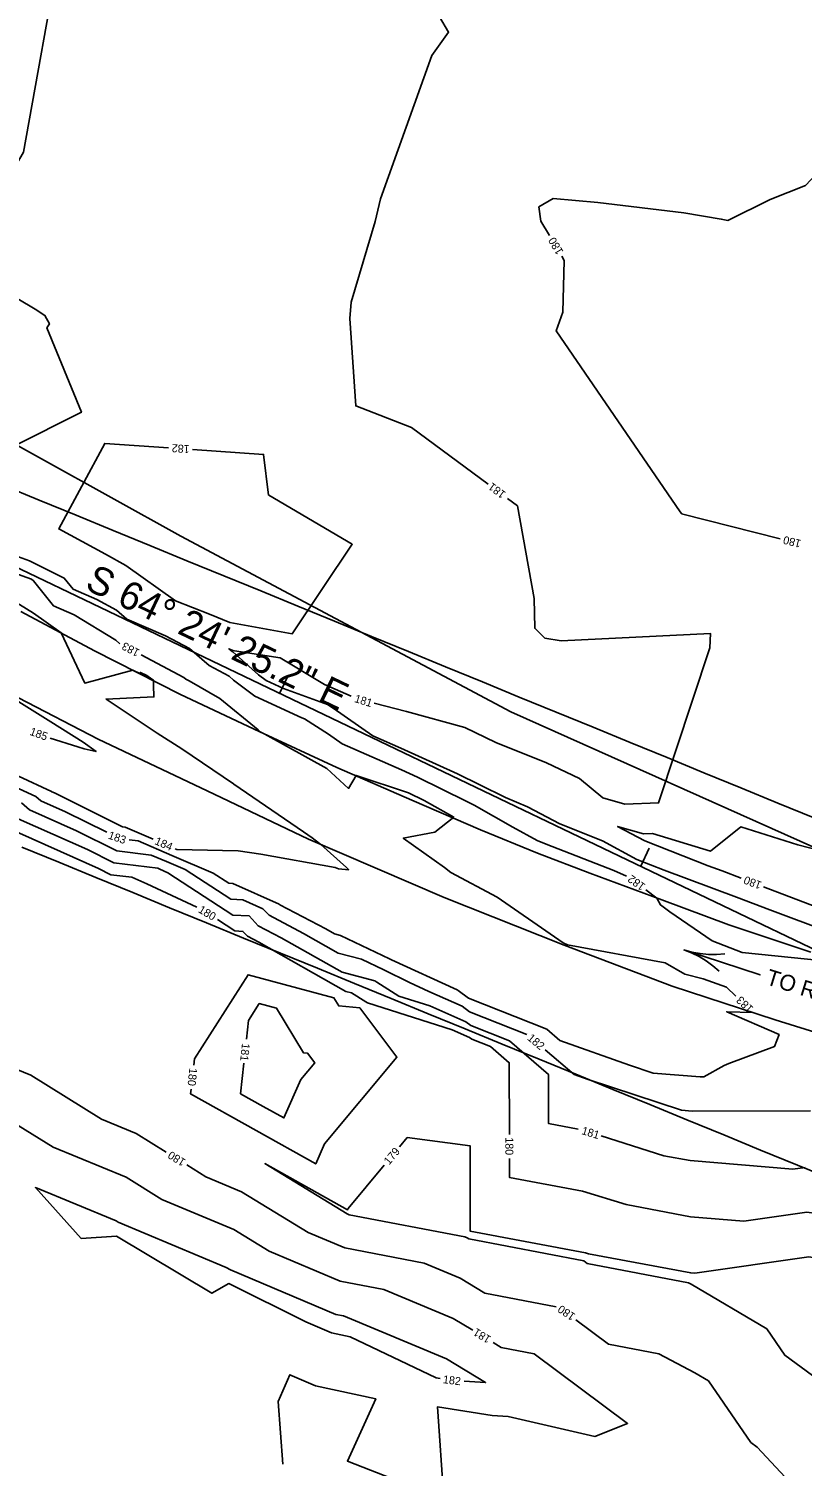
# Model space of a CAD drawing. Extents: x 2086416 to 2115205, y 575507 to 632762.
# Drawn here: x 2110664.3 to 2110857.5, y 581552.3 to 581911.5 of the extents above; entities that cross this region are included whole.
import ezdxf

# ---------------------------------------------------------------- set-up
doc = ezdxf.new("R2010")
doc.units = 0
for name, color, linetype in [('Default', 7, 'Continuous'), ('DTM Contours Major', 7, 'Continuous'), ('DTM Contours Major Text', 7, 'Continuous'), ('DTM Contours Minor', 7, 'Continuous'), ('DTM Contours Minor Text', 7, 'Continuous'), ('Exist Hydrographic FEMA Cross Section', 7, 'Continuous'), ('Exist Roads EOP', 7, 'Continuous'), ('Exist Roads EOP Text', 7, 'Continuous'), ('Exist Vegetation Woods Line', 7, 'Continuous')]:
    doc.layers.add(name, color=color, linetype=linetype)

msp = doc.modelspace()

# ---------------------------------------------------------------- linework, layer by layer
at = {"layer": 'Default'}
for p, q in [((2110456.37, 581874.95), (2110974.98, 581626.56)), ((2110726.94, 581745.36), (2110729.1, 581749.87)), ((2110817.13, 581702.16), (2110819.29, 581706.67))]:
    msp.add_line(p, q, dxfattribs=at)
at = {"layer": 'DTM Contours Major'}
for points in [[(2110875.11, 581887.46), (2110869.25, 581883.98), (2110858.27, 581872.27), (2110849.5, 581868.78), (2110838.87, 581863.56), (2110837.24, 581863.88), (2110827.93, 581865.43), (2110806.43, 581868), (2110795.23, 581869.03), (2110791.72, 581866.92), (2110792.22, 581863.37), (2110794.35, 581859.78)], [(2110797.42, 581854.62), (2110798.05, 581853.55), (2110797.69, 581840.6), (2110795.99, 581835.94), (2110827.03, 581790.7), (2110827.32, 581790.29), (2110827.36, 581790.26), (2110852, 581783.99)], [(2110613.93, 581787.13), (2110614.2, 581786.7), (2110617.97, 581783.15), (2110627.86, 581773.78), (2110633.68, 581769.53), (2110635.48, 581767.5), (2110642.91, 581758.9), (2110656.28, 581747.21), (2110658.07, 581745.98), (2110659.68, 581744.77), (2110661.17, 581743.69), (2110669.84, 581738.28), (2110677.86, 581733.15), (2110681.1, 581730.87), (2110678.11, 581731.54), (2110676.51, 581732.02), (2110669.66, 581734.22)], [(2110706.28, 581691.93), (2110693.8, 581697.81), (2110690.01, 581699.43), (2110684.82, 581700.07), (2110681.7, 581701.62), (2110658.82, 581711.83), (2110658.38, 581712.2), (2110655.34, 581713.32), (2110650.98, 581714.55), (2110621.94, 581701.5), (2110616.68, 581704.25), (2110614.73, 581705.26)], [(2110873.53, 581703.08), (2110856.38, 581707.56), (2110842.13, 581711.99), (2110834.59, 581705.91), (2110820.11, 581710.34), (2110817.82, 581710.24), (2110811.38, 581712.14), (2110818.2, 581708.5), (2110833.97, 581702.31), (2110837.45, 581701), (2110842.24, 581699.17)], [(2110847.85, 581697.03), (2110861.11, 581691.96), (2110865.83, 581690.2), (2110868.29, 581689.26), (2110879.23, 581683.6), (2110880.71, 581683.05), (2110888.09, 581682.6), (2110898.02, 581678.3), (2110910.04, 581674.42), (2110913.9, 581674.27), (2110914.63, 581674.08), (2110929.32, 581669.43), (2110931.83, 581667.74), (2110941.39, 581664.51), (2110941.63, 581664.47)], [(2110784.33, 581635.17), (2110784.32, 581653.09), (2110779.63, 581657.15), (2110774.99, 581658.99), (2110774.4, 581659.43), (2110770.07, 581661.34), (2110748.91, 581668.01), (2110748.44, 581668.31), (2110744.94, 581670.52), (2110743.47, 581670.91), (2110721.78, 581683.2), (2110718.94, 581684.68), (2110717.79, 581685.89), (2110715.79, 581686.01), (2110711.42, 581688.85)], [(2110614.54, 581679.26), (2110619.08, 581680.34), (2110637.66, 581668.88), (2110655.14, 581658.09), (2110656.42, 581653.38), (2110664.82, 581649.96), (2110682.42, 581638.95), (2110691.1, 581635.36), (2110698.64, 581630.7)], [(2110738.13, 581632.78), (2110756.23, 581654.5), (2110746.95, 581666.78), (2110741.73, 581667.28), (2110740.52, 581669.29), (2110719.05, 581675.06), (2110705.66, 581654.02), (2110705.49, 581652.46)], [(2110704.85, 581646.49), (2110704.72, 581645.3), (2110721.08, 581636.15), (2110735.97, 581627.82), (2110738.13, 581632.78)], [(2110876.9, 581608.98), (2110875.97, 581608.94), (2110861.02, 581615.41), (2110858.67, 581615.72), (2110842.9, 581613.47), (2110829.57, 581614.6), (2110813.49, 581617.62), (2110802.61, 581621.03), (2110784.33, 581624.43), (2110784.33, 581629.17)], [(2110703.74, 581627.54), (2110708.49, 581624.6), (2110717.43, 581620.86), (2110734.08, 581610.65), (2110743.22, 581606.79), (2110763.09, 581602.99), (2110772.06, 581599.26), (2110778.24, 581595.53), (2110796.02, 581592.11)], [(2110800.95, 581588.81), (2110809.09, 581582.72), (2110821.66, 581580.31), (2110830.66, 581575.58), (2110834.04, 581573.59), (2110844.63, 581558.22), (2110846.26, 581557.03), (2110861.48, 581540.67), (2110862.45, 581535.67), (2110855.94, 581535.48), (2110849.88, 581541.19)]]:
    msp.add_lwpolyline(points, dxfattribs=at)
at = {"layer": 'DTM Contours Minor'}
for points in [[(2110775.86, 581953.5), (2110764.32, 581958.22), (2110760.24, 581943.47), (2110768.82, 581917.19), (2110766.89, 581914.46), (2110769.13, 581910.61), (2110764.97, 581904.78), (2110752.13, 581868.98), (2110750.83, 581863.28), (2110744.81, 581843.13), (2110744.47, 581839.04), (2110745.98, 581817.21), (2110759.85, 581811.8), (2110779.05, 581797.65)], [(2110672.37, 581932.97), (2110662.96, 581880.6), (2110650.69, 581859.37), (2110649.72, 581851), (2110665.85, 581841.38), (2110668.3, 581839.83), (2110669.46, 581837.68), (2110668.83, 581836.73), (2110677.42, 581815.61), (2110643.22, 581798.5), (2110629.19, 581802.12), (2110627.72, 581804.48), (2110627.29, 581802.33), (2110628.54, 581801.21), (2110629.18, 581800.63), (2110629.48, 581800.67), (2110633.9, 581797.89)], [(2110699.21, 581806.73), (2110683.26, 581807.82), (2110671.77, 581786.48), (2110683.44, 581780.2), (2110688.54, 581777.3), (2110700.9, 581768.53), (2110709.47, 581765.13), (2110714.47, 581763.07)], [(2110714.47, 581763.07), (2110730.11, 581760.27), (2110745.1, 581782.66), (2110724.29, 581794.88), (2110724.2, 581794.91), (2110722.93, 581805.1), (2110705.19, 581806.32)], [(2110783.88, 581794.09), (2110786.38, 581792.24), (2110790.55, 581769.06), (2110790.67, 581761.66), (2110793.22, 581759.21), (2110797.3, 581758.53), (2110834.58, 581760.33), (2110834.42, 581756.77), (2110821.6, 581718.02), (2110813.16, 581717.66), (2110807.7, 581719.27), (2110801.81, 581724.13), (2110793.61, 581728.02), (2110780.97, 581733.08), (2110773.17, 581736.89), (2110758.67, 581740.86), (2110750.54, 581742.89)], [(2110659.86, 581780.13), (2110664.5, 581778.47), (2110673.17, 581774.14), (2110675.37, 581771.42), (2110681.32, 581768.8), (2110686.2, 581766.18), (2110688.77, 581763.93), (2110698.41, 581759.72), (2110704.41, 581756.57), (2110709.32, 581752.37), (2110714.34, 581749.66), (2110715.43, 581748.68), (2110720.79, 581744.69), (2110732.5, 581739.25), (2110733.16, 581739.01), (2110739.12, 581735.16), (2110742.54, 581732.77), (2110757.35, 581726.29), (2110761.4, 581724.45), (2110773.69, 581718.38), (2110775.58, 581717.45), (2110785.2, 581711.98), (2110791.25, 581708.61), (2110793.49, 581707.73), (2110810.4, 581701.16), (2110813.56, 581699.74)], [(2110653.98, 581777.82), (2110665, 581773.88), (2110665.48, 581773.5), (2110670.48, 581767.29), (2110675.64, 581765.02), (2110686.01, 581758.67), (2110687.06, 581757.75)], [(2110654.46, 581772.18), (2110665.46, 581765.46), (2110672.35, 581760.51), (2110678.29, 581747.94), (2110690.29, 581751.21), (2110691.99, 581750.37), (2110692.19, 581750.63), (2110693.8, 581749.81), (2110695.06, 581748.94), (2110695.41, 581748.69), (2110695.46, 581747.45), (2110695.55, 581744.5), (2110683.59, 581743.96), (2110696.4, 581735.45), (2110702.5, 581731.53), (2110715.41, 581722.75), (2110715.47, 581722.71), (2110732.91, 581710.78), (2110735.1, 581709.24), (2110737.26, 581707.64), (2110743.62, 581701.84), (2110744.21, 581701.3), (2110741.62, 581701.53), (2110740.86, 581701.85), (2110722.22, 581705.24), (2110716.61, 581706.04), (2110712.68, 581706.13), (2110701.37, 581706.37), (2110701.31, 581706.38), (2110701.24, 581706.39), (2110700.82, 581706.57)], [(2110692.36, 581754.97), (2110702.99, 581749.38), (2110703.53, 581748.93), (2110704.33, 581748.49), (2110711.97, 581744.12), (2110721.57, 581736.26), (2110722.09, 581735.79), (2110723.27, 581735.2), (2110738.74, 581726.59), (2110744.19, 581721.64), (2110746.05, 581724.86), (2110759.16, 581720.54), (2110763.09, 581718.65), (2110770.46, 581714.45), (2110765.74, 581710.68), (2110757.84, 581709.2), (2110768.09, 581701.86), (2110769.74, 581700.6), (2110781.3, 581694.48), (2110795.58, 581684.55), (2110797.77, 581683.02), (2110798.85, 581682.54), (2110823.21, 581678.05), (2110828.17, 581675.21), (2110832.75, 581674.08), (2110838.55, 581671.95), (2110840.9, 581669.72)], [(2110744.84, 581744.68), (2110738.18, 581747.62), (2110727.08, 581754.3), (2110715.7, 581756.04), (2110715.25, 581756.12), (2110714.3, 581756.51), (2110715.11, 581755.81), (2110715.25, 581755.74), (2110721.64, 581750.04), (2110723.61, 581748.57), (2110727.93, 581746.56), (2110738.89, 581742.6), (2110740.3, 581741.69), (2110750.22, 581734.74), (2110757.2, 581731.69), (2110771.37, 581725.27), (2110776.96, 581722.51), (2110783.38, 581719.36), (2110788.87, 581717), (2110796.93, 581712.8), (2110807.57, 581708.49), (2110816.16, 581703.9), (2110822.98, 581701.22), (2110841.1, 581694.44), (2110849.4, 581691.27), (2110864.3, 581685.71)], [(2110695.32, 581708.96), (2110688.38, 581711.98), (2110687.7, 581712.06), (2110670.71, 581720.49), (2110670.08, 581720.77), (2110669.96, 581720.88), (2110653.37, 581728.55)], [(2110683.75, 581710.67), (2110673.46, 581715.77), (2110667.27, 581718.53), (2110666.02, 581719.6), (2110658.64, 581723.02)], [(2110788.71, 581660.14), (2110774.39, 581665.82), (2110772.51, 581667.23), (2110764.23, 581670.88), (2110759.35, 581673.12), (2110752.95, 581676.29), (2110747.39, 581678.96), (2110741.61, 581680.5), (2110732.94, 581685.41), (2110724.31, 581689.93), (2110722.74, 581691.58), (2110717.79, 581693.79), (2110714.74, 581693.96), (2110703.39, 581701.35), (2110698.68, 581703.34), (2110694.89, 581704.99), (2110686.26, 581706.07), (2110676.21, 581711.05), (2110664.45, 581716.3), (2110662.47, 581718.01)], [(2110801.48, 581636.52), (2110794.09, 581637.9), (2110794.08, 581650.15), (2110784.33, 581658.58), (2110774.69, 581662.4), (2110773.46, 581663.33), (2110764.45, 581667.3), (2110756.74, 581669.73), (2110751.23, 581673.2), (2110750.71, 581673.53), (2110742.54, 581675.71), (2110727.36, 581684.3), (2110721.62, 581687.31), (2110719.3, 581689.75), (2110715.26, 581689.99), (2110699.06, 581700.52), (2110697.04, 581701.47), (2110696.5, 581701.71), (2110685.54, 581703.07), (2110678.96, 581706.34), (2110661.63, 581714.06)], [(2110845.22, 581665.6), (2110838.61, 581665.84), (2110851.69, 581660.12), (2110850.58, 581657.12), (2110839.13, 581652.88), (2110837.96, 581652.36), (2110832.9, 581649.56), (2110831.96, 581649.56), (2110820.28, 581650.5), (2110814.3, 581652.46), (2110796.93, 581658.68), (2110793.73, 581661.45), (2110774.09, 581669.24), (2110771.57, 581671.12), (2110771.27, 581671.26), (2110754.92, 581678.76), (2110754.43, 581679.01), (2110742.11, 581684.91), (2110740.67, 581685.29), (2110738.52, 581686.51), (2110726.99, 581692.55), (2110726.82, 581692.73), (2110715.25, 581697.88), (2110714.22, 581697.94), (2110710.36, 581700.45), (2110700, 581704.85), (2110691.63, 581708.49), (2110689.36, 581708.77)], [(2110818.44, 581696.27), (2110821.2, 581694.21), (2110822.09, 581692.5), (2110824.38, 581690.77), (2110834.99, 581683.55), (2110842.52, 581680.61), (2110862.89, 581678.56)], [(2110604.39, 581671.28), (2110610.61, 581661.99), (2110624.31, 581665.25), (2110632.56, 581660.16), (2110640.32, 581655.37), (2110643.15, 581644.99), (2110661.66, 581637.44), (2110670.37, 581631.99), (2110688.6, 581624.45), (2110697.54, 581618.92), (2110715.51, 581611.4), (2110724.37, 581605.97), (2110742.09, 581598.48), (2110752.98, 581596.4), (2110770.33, 581589.17), (2110775.18, 581586.24)], [(2110732.22, 581648.91), (2110735.7, 581653.09), (2110733.91, 581655.45), (2110732.91, 581655.54), (2110726.18, 581666.71), (2110721.86, 581667.87), (2110719.16, 581663.63), (2110718.66, 581658.97)], [(2110859.55, 581641.04), (2110830.03, 581640.99), (2110827.32, 581641.21), (2110803.98, 581648.87), (2110800.48, 581650.12), (2110793.31, 581656.32)], [(2110718.03, 581653), (2110717.21, 581645.33), (2110722.87, 581642.16), (2110728.03, 581639.28), (2110732.22, 581648.91)], [(2110929.04, 581613.04), (2110920.49, 581613.95), (2110917.95, 581613.11), (2110916.27, 581613.41), (2110901.27, 581603.04), (2110890.27, 581602.57), (2110889.9, 581602.71), (2110866.52, 581601.67), (2110860.13, 581604.43), (2110859.13, 581604.56), (2110830.62, 581600.5), (2110829.64, 581600.58), (2110804.08, 581605.37), (2110803.32, 581605.61), (2110774.57, 581610.97), (2110774.57, 581632.28), (2110758.83, 581634.4), (2110756.92, 581632.1)], [(2110858.22, 581626.88), (2110855.17, 581626.45), (2110829.5, 581628.62), (2110822.89, 581629.86), (2110807.22, 581634.78)], [(2110753.08, 581627.49), (2110744.05, 581616.65), (2110743.92, 581616.36), (2110723.28, 581627.9), (2110743.8, 581615.32), (2110744.35, 581615.09), (2110773.2, 581609.58), (2110773.78, 581609.34), (2110774.18, 581609.1), (2110802.91, 581603.58), (2110803.77, 581602.94), (2110829.06, 581598.07), (2110829.72, 581597.73), (2110848.6, 581586.56), (2110853.13, 581580), (2110864.1, 581571.94), (2110868.48, 581567.23)], [(2110742.87, 581589.81), (2110740.96, 581590.18), (2110714.65, 581601.3), (2110713.6, 581601.94), (2110686.58, 581613.24), (2110686.1, 581613.54), (2110665.95, 581621.88), (2110677.38, 581609.19), (2110686.18, 581609.76), (2110710, 581595.5), (2110714.28, 581597.88), (2110733.49, 581588.34), (2110739.88, 581585.59), (2110744.53, 581584.59), (2110766.06, 581574.38), (2110767.08, 581574.21)], [(2110773.03, 581573.48), (2110778.41, 581573.17), (2110768.6, 581579.09), (2110742.87, 581589.81)], [(2110780.32, 581583.14), (2110782.3, 581581.95), (2110790.5, 581580.38), (2110813.88, 581562.9), (2110805.64, 581559.71), (2110784.07, 581564.67), (2110780.03, 581564.9), (2110766.38, 581567.1), (2110767.94, 581544.14), (2110743.89, 581553.54), (2110750.95, 581569.13), (2110735.94, 581572.34), (2110729.52, 581575.11), (2110726.6, 581568.42), (2110727.73, 581552.75)]]:
    msp.add_lwpolyline(points, dxfattribs=at)
at = {"layer": 'Exist Hydrographic FEMA Cross Section'}
for points in [[(2110860.61, 581714.19), (2110851.39, 581717.98), (2110842.16, 581721.76), (2110832.94, 581725.55), (2110823.71, 581729.33), (2110814.49, 581733.12), (2110805.27, 581736.9), (2110796.04, 581740.69), (2110786.81, 581744.47), (2110777.59, 581748.26), (2110768.36, 581752.04), (2110759.14, 581755.83), (2110749.91, 581759.61), (2110740.69, 581763.39), (2110731.46, 581767.18), (2110722.23, 581770.97), (2110713.01, 581774.75), (2110703.79, 581778.53), (2110694.56, 581782.32), (2110685.33, 581786.1), (2110676.11, 581789.89), (2110666.89, 581793.68), (2110657.66, 581797.46)], [(2110865.54, 581623.7), (2110856.32, 581627.48), (2110847.09, 581631.27), (2110837.86, 581635.05), (2110828.64, 581638.84), (2110819.42, 581642.62), (2110810.19, 581646.4), (2110800.96, 581650.19), (2110791.74, 581653.98), (2110782.52, 581657.76), (2110773.29, 581661.54), (2110764.06, 581665.33), (2110754.84, 581669.11), (2110745.61, 581672.9), (2110736.39, 581676.69), (2110727.16, 581680.47), (2110717.94, 581684.25), (2110708.71, 581688.04), (2110699.48, 581691.82), (2110690.26, 581695.61), (2110681.04, 581699.39), (2110671.81, 581703.18), (2110662.58, 581706.96)]]:
    msp.add_lwpolyline(points, dxfattribs=at)
at = {"layer": 'Exist Roads EOP'}
for points in [[(2110859.62, 581680.71), (2110839.18, 581687.57), (2110822.39, 581693.78), (2110804.41, 581700.49), (2110791.36, 581705.43), (2110777.14, 581711.28), (2110760, 581718.68), (2110741.24, 581726.89), (2110721.85, 581735.85), (2110702.22, 581745.1), (2110680.73, 581755.98), (2110662.27, 581765.85)], [(2110661.71, 581744.29), (2110681.63, 581733.96), (2110708.85, 581721.01), (2110734.15, 581708.98), (2110768.01, 581694.36), (2110797.99, 581682.47), (2110825.02, 581672.22), (2110850.72, 581663.8), (2110872.12, 581657.17), (2110892.09, 581651.25), (2110910.76, 581646.06), (2110929.15, 581641.61), (2110951.61, 581636.54), (2110973.54, 581631.44)]]:
    msp.add_lwpolyline(points, dxfattribs=at)
at = {"layer": 'Exist Roads EOP Text'}
msp.add_line((2110837.43, 581678.14), (2110837.43, 581678.14), dxfattribs=at)
msp.add_lwpolyline([(2110836.72, 581675.97), (2110835.17, 581677.31), (2110833.49, 581678.53), (2110831.71, 581679.61), (2110829.86, 581680.55), (2110827.93, 581681.26), (2110846.94, 581675.03), (2110827.93, 581681.26), (2110829.9, 581680.69), (2110831.95, 581680.35), (2110834.03, 581680.17), (2110836.11, 581680.16), (2110838.15, 581680.32)], dxfattribs=at)
at = {"layer": 'Exist Vegetation Woods Line'}
msp.add_lwpolyline([(2111059.79, 581657.65), (2110968.73, 581672.25), (2110864.06, 581705.25), (2110784.73, 581740.8), (2110702.3, 581784.67), (2110632.54, 581823.34), (2110568.48, 581865.95), (2110498.27, 581913.79), (2110441.66, 581966.78), (2110387.94, 582016.39), (2110334.43, 582063.69), (2110284.48, 582120.87)], dxfattribs=at)

# ---------------------------------------------------------------- texts
at = {"layer": 'Default'}
msp.add_text('S 64%%d 24\' 25.2" E', height=7, rotation=334.407, dxfattribs=at).set_placement((2110678.01, 581771.57))
at = {"layer": 'DTM Contours Major Text'}
for s, rotation, p in [('180', 120.6948, (2110797.91, 581855.75)), ('180', 165.7175, (2110857.36, 581783.65)), ('185', 340.1435, (2110664.36, 581735.06)), ('180', 159.0867, (2110847.53, 581698.22)), ('180', 329.0924, (2110706.44, 581690.8)), ('180', 263.899, (2110704.42, 581651.84)), ('180', 270.0188, (2110783.33, 581634.45)), ('180', 148.2468, (2110703.65, 581628.77)), ('180', 146.1671, (2110801, 581590.17))]:
    msp.add_text(s, height=2, rotation=rotation, dxfattribs=at).set_placement(p)
at = {"layer": 'DTM Contours Minor Text'}
for s, rotation, p in [('182', 176.0842, (2110704.54, 581807.36)), ('181', 143.6087, (2110783.61, 581795.52)), ('183', 152.3918, (2110692.18, 581756.2)), ('181', 342.5962, (2110745.48, 581743.25)), ('183', 341.2986, (2110683.96, 581709.12)), ('184', 336.5277, (2110695.58, 581707.76)), ('182', 144.5653, (2110818.47, 581697.56)), ('183', 136.412, (2110845.42, 581666.81)), ('181', 263.899, (2110717.56, 581658.02)), ('182', 320.256, (2110788.65, 581658.97)), ('181', 343.087, (2110802.21, 581635.28)), ('179', 50.1912, (2110754.31, 581627.41)), ('181', 148.8935, (2110779.93, 581584.55)), ('182', 353.0143, (2110767.66, 581573.02))]:
    msp.add_text(s, height=2, rotation=rotation, dxfattribs=at).set_placement(p)
at = {"layer": 'Exist Roads EOP Text'}
msp.add_text('TO REDHILL CHURCH RD', height=4, rotation=342.7594, dxfattribs=at).set_placement((2110848.16, 581672.74))

doc.saveas('drawing.dxf')
